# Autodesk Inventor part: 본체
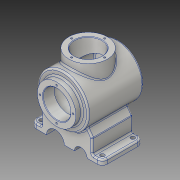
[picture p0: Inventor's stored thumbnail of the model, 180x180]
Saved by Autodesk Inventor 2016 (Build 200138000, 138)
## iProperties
Created: 2018-08
Part Number: 본체
Material: 알루미늄 6061
Document SubType Name: Modeling
Designer: MIRAE
Mass: 1965.21 g
Surface Area: 1152.32 cm^2
Volume: 727.857 cm^3
Density: 2.7 g/cm^3
Appearance: 알루미늄 - 평지
Author: MIRAE
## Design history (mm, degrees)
sketch "스케치1"
  geometry: L1 (0, 0)-(131.329, 0); L2 (0, 0)-(0, 38); L3 (0, 38)-(12, 38); L4 (12, 38)-(12, 50); L5 (12, 50)-(66.141, 50); L6 (66.141, 50)-(120, 50); L7 (120, 50)-(120, 38); A1 r 116 centre (15.329, 0) between (131.329, 0) and (120, 50)
  constraints: 14 end point, 4 perpendicular, 3 point on line, 2 point on circle, 1 centre point, 1 horizontal, 1 vertical
  dimensions: "d0" = 76 diameter of L3 L1; "d1" = 100 diameter of L5 L1; "d2" = 120 distance between parallel lines of L7 L2; "d3" = 12 distance between parallel lines of L4 L2; "d4" = 116 radius of A1
node "작업 평면1"
revolve "회전1" stored, may be unused: angle "d11" = 90 deg
sketch "스케치3"
  geometry: L1 (0, 0)-(131.669, 0); L2 (0, 0)-(0, 27); L3 (0, -38)-(0, 38) reference; L4 (0, 27)-(22, 27); L5 (22, 27)-(22, 40); L6 (22, 40)-(113.492, 40); A1 r 116 centre (15.329, 0) between (120, -50) and (120, 50) reference; A2 r 106 centre (15.329, 0) between (121.329, 0) and (113.492, 40)
  constraints: 10 end point, 2 horizontal, 2 perpendicular, 2 point on circle, 2 point on line, 1 centre point
  dimensions: "d12" = 10 radial gap between concentric circles of A1 A2; "d13" = 54 diameter of L4 L1; "d14" = 80 diameter of L6 L1; "d15" = 22 distance between parallel lines of L5 L2
revolve "회전2" sketch "스케치3" stored, may be unused: angle "d16" = 90 deg
sketch "스케치5" dims "d17" = 65
  geometry: L1 (0, 0)-(0, 32.5); C1 r 38 at (0, 0) reference; 2 further points
  constraints: 2 coincident, 2 end point, 1 vertical, 1 vertical alignment, 2 other
hole "구멍1" sketch "스케치5" at (0, 32.5) diameter "d18" = 3.459; stored, may be unused: countersink angle "d22" = 90 deg, drill point angle "d24" = 118 deg; dims "d19" = 8, "d20" = 4, "d21" = 2, "d23" = 10
node "작업 평면2"
sketch "스케치8"
  geometry: L1 (12, 50)-(120, 50) reference; L2 (12, -50)-(120, -50) reference; L3 (0, -38)-(0, 38) reference; L4 (0, 0)-(131.329, 0); L5 (20, -70)-(100, -70); L6 (100, -70)-(100, 70); L7 (100, 70)-(20, 70); L8 (20, 70)-(20, -70); L9 (20, -70)-(100, 70); L10 (100, -70)-(20, 70); L11 (12, -50)-(12, 50) reference; A1 r 116 centre (15.329, 0) between (120, -50) and (120, 50) reference; 1 further point
  constraints: 14 end point, 2 midpoint, 2 parallel, 1 horizontal, 1 perpendicular, 1 point on circle, 1 point on line
  dimensions: "d36" = 80 distance of L7.end L6.end; "d37" = 140 distance between parallel lines of L5 L7; "d38" = 8 distance between parallel lines of L8 L11
extrude "돌출1" join sketch "스케치8" distance "d39" = 10; taper "d40" = 0 deg
fillet "모깎기1" dims "d41" = 10
sketch "스케치10"
  geometry: A1 r 10 centre (30, 60) between (30, 70) and (20, 60) reference; A2 r 10 centre (90, 60) between (100, 60) and (90, 70) reference; A3 r 10 centre (90, -60) between (90, -70) and (100, -60) reference; A4 r 10 centre (30, -60) between (20, -60) and (30, -70) reference; 1 further point
hole "구멍2" sketch "스케치10" at (30, -60), (90, -60), (30, 60), (90, 60) diameter "d42" = 8; stored, may be unused: countersink angle "d46" = 90 deg, drill point angle "d48" = 118 deg; dims "d43" = 8, "d44" = 4, "d45" = 2, "d47" = 10
node "작업 평면4"
sketch "스케치11"
  geometry: L1 (0, 0)-(120, 0) reference; L2 (0, 10)-(120, 10) reference; C1 r 50 at (60, 82) reference; 1 further point
sketch "스케치12"
  geometry: L1 (60, 32)-(60, 10); L2 (130, 10)-(130, 0) reference; L3 (130, 10)-(110, 10); L4 (120, 10)-(0, 10) reference; L5 (110, 10)-(110, 38.563); L6 (110, 38.563)-(100.304, 52.41); L7 (60, 10)-(110, 10); L8 (60, 10)-(60, 82); L9 (120, 10)-(130, 10) reference; L10 (130, 10)-(100.304, 52.41); A1 r 50 centre (60, 82) between (100.304, 52.41) and (60, 32) reference; A2 r 50 centre (60, 82) between (60, 32) and (100.304, 52.41); 1 further point
  constraints: 14 end point, 5 point on circle, 3 collinear, 2 point on line, 1 centre point, 1 coincident, 1 concentric, 1 midpoint, 1 perpendicular, 1 vertical
  dimensions: "d49" = 20 distance of L2.start L3.end; "d56" = 35 deg angle of L10 L2
extrude "돌출2" join sketch "스케치12" stored distance "d57" = 80; taper "d58" = 0 deg
sketch "스케치15"
  geometry: L1 (0, 10)-(120, 10) reference; L2 (-10, 0)-(-10, 10) reference; L3 (-10, 10)-(0, 10) reference; L4 (-10, 10)-(74.021, 129.994); L5 (-10, 10)-(10, 10); L6 (60, 10)-(0, 10) reference; L7 (10, 10)-(10, 38.563); L8 (10, 38.563)-(19.696, 52.41); L9 (10, 10)-(60, 10); L10 (60, 10)-(60, 32) reference; L11 (60, 10)-(60, 32); A1 r 50 centre (60, 82) between (19.696, 52.41) and (60, 32); 1 further point
  constraints: 12 end point, 3 collinear, 3 point on circle, 3 point on line, 1 centre point, 1 coincident, 1 vertical
  dimensions: "d59" = 35 deg angle of L4 L2; "d60" = 20 distance of L2.end L5.end
extrude "돌출3" join sketch "스케치15" stored distance "d61" = 80; taper "d62" = 0 deg
sketch "스케치16"
  geometry: L1 (0, 0)-(0, 120) reference; L2 (0, 130)-(-10, 130) reference; L3 (-10, -10)-(0, -10) reference; L4 (0, 60)-(-27.175, 60); L5 (0, 60)-(0, 82.5); L6 (0, 60)-(0, 32.5); C1 r 17.5 at (0, 82.5); C2 r 12.5 at (0, 32.5); 3 further points
  constraints: 6 end point, 4 coincident, 2 centre point, 2 point on line, 1 horizontal, 1 midpoint
  dimensions: "d63" = 22.5 distance of L4.start L5.end; "d64" = 35 diameter of C1; "d65" = 27.5 distance of L4.start L6.end; "d66" = 25 diameter of C2
extrude "돌출4" cut sketch "스케치16" stored distance "d67" = 80; taper "d68" = 0 deg
node "작업 평면5"
sketch "스케치17"
  geometry: L1 (30, -70)-(90, -70) reference; L2 (12, -50)-(12, 50) reference; L3 (20, -50)-(20, -60) reference; L4 (62, 31.339)-(62, -29.854); L5 (0, -38)-(0, 38) reference; L6 (0, 0)-(112.138, 0); C1 r 38 at (62, 0); 1 further point
  constraints: 4 end point, 2 point on line, 1 centre point, 1 coincident, 1 horizontal, 1 vertical
  dimensions: "d98" = 62 distance between parallel lines of L4 L5; "d100" = 76 diameter of C1
extrude "돌출5" join sketch "스케치17" stored distance "d71" = 80; taper "d72" = 0 deg
sketch "스케치18"
  geometry: C1 r 38 at (0, 0) reference; C2 r 27 at (0, 0); 1 further point
  constraints: 1 centre point, 1 coincident
  dimensions: "d73" = 54 diameter of C2
extrude "돌출6" cut sketch "스케치18" stored distance "d74" = 80; taper "d75" = 0 deg
sketch "스케치19" dims "d76" = 65
  geometry: L1 (0, 0)-(0, 32.5); C1 r 27 at (0, 0) reference; 2 further points
  constraints: 2 coincident, 2 end point, 1 vertical, 1 vertical alignment, 2 other
hole "구멍3" sketch "스케치19" at (0, 32.5) diameter "d77" = 3.459; stored, may be unused: countersink angle "d81" = 90 deg, drill point angle "d83" = 118 deg; dims "d78" = 8, "d79" = 4, "d80" = 2, "d82" = 10.8
node "작업 평면6"
sketch "스케치20"
  geometry: L1 (0, 0)-(0, 59.6); C1 r 32.5 at (0, 0); 1 further point
  constraints: 2 end point, 1 centre point, 1 coincident, 1 vertical, 1 other
  dimensions: "d87" = 65 diameter of C1
feature "엠보싱1" sketch "스케치20" dims "d12" = 10, "d13" = 54, "d14" = 80, "d15" = 22, "d88" = 0.5, "d89" = 0
chamfer "모따기1" distance "d90" = 1; stored, may be unused: second distance "d91" = 2, angle "d92" = 45 deg
fillet "모깎기2" dims "d93" = 3
fillet "모깎기3" dims "d94" = 3
fillet "모깎기4" dims "d95" = 3
fillet "모깎기5" dims "d96" = 3
fillet "모깎기6" dims "d97" = 3
fillet "모깎기7" dims "d101" = 3
fillet "모깎기8" dims "d102" = 3
chamfer "모따기2" distance "d103" = 1; stored, may be unused: second distance "d104" = 2, angle "d105" = 45 deg
node "솔리드1"
pattern_circular "원형 패턴1" dims angle "d26" = 360 deg
pattern_circular "원형 패턴2" dims angle "d85" = 360 deg
node "투영된 루프1"
other parameters: "d6" = 0, "d28" = -82, "d69" = -147
